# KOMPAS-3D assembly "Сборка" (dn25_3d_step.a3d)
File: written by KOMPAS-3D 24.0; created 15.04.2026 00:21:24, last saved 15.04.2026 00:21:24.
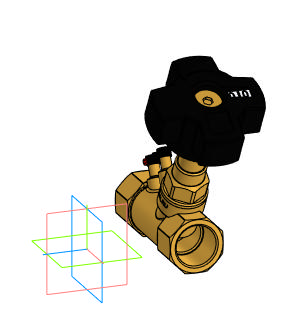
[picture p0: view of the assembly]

Document properties: Автор: tyuri; Полное имя файла: D:\Аутсорс\VB0000P-T Клапан балансировочный статический DN.ru\DN25\dn25_3d_step.a3d

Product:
- Component [detail]: Деталь1  | qty 1  | Автор: tyuri; source file: Деталь1 - Деталь1.m3d
- Component [detail]: Деталь2  | qty 1  | Автор: tyuri; source file: Деталь2 - Деталь2.m3d
- Part/product: Сборка

Referenced files in D:\Аутсорс\VB0000P-T Клапан балансировочный статический DN.ru\DN25\: Деталь1 - Деталь1.m3d, Деталь2 - Деталь2.m3d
